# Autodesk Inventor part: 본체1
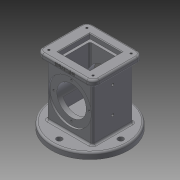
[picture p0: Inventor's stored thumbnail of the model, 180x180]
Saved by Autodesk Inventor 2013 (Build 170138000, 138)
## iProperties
Created: 2018-10
Part Number: 본체1
Material: Generic
Document SubType Name: Modeling
Designer: Administrator
Density: 1 g/cm^3
Author: Administrator
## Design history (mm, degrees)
sketch "스케치1"
  geometry: C1 r 62.5 at (0, 0); 1 further point
  constraints: 1 centre point, 1 coincident
extrude "돌출1" new body sketch "스케치1" distance "d1" = 10; taper "d2" = 0 deg
sketch "스케치2"
  geometry: C1 r 62.5 at (0, 0) reference; A1 r 50 centre (0, 0) between (0, 50) and (50, 0); 2 further points
  constraints: 4 point on circle, 1 centre point, 1 coincident
  dimensions: "d3" = 100 diameter of A1
hole "구멍1" sketch "스케치2" at (0, 50), (50, 0), (0, -50), (-50, 0) diameter "d4" = 9; stored, may be unused: countersink angle "d8" = 90 deg, drill point angle "d10" = 118 deg; dims "d5" = 6, "d6" = 4, "d7" = 2, "d9" = 8
sketch "스케치3"
  geometry: L1 (-37, 33)-(37, 33); L2 (37, 33)-(37, -33); L3 (37, -33)-(-37, -33); L4 (-37, -33)-(-37, 33); C1 r 62.5 at (0, 0) reference; 2 further points
  constraints: 8 end point, 2 midpoint, 2 parallel, 1 horizontal, 1 horizontal alignment, 1 perpendicular, 1 vertical alignment
  dimensions: "d11" = 74 distance of L1.start L1.end; "d13" = 66 distance of L1.end L2.end
extrude "돌출2" join sketch "스케치3" distance "d14" = 98; taper "d15" = 0 deg
sketch "스케치4"
  geometry: L1 (37, 33)-(-37, 33) reference; L2 (-37, 33)-(-37, -33) reference; L3 (-37, -33)-(37, -33) reference; L4 (37, -33)-(37, 33) reference; L5 (-46, 41)-(46, 41); L6 (46, 41)-(46, -41); L7 (46, -41)-(-46, -41); L8 (-46, -41)-(-46, 41); 3 further points
  constraints: 8 end point, 2 midpoint, 2 parallel, 1 horizontal, 1 horizontal alignment, 1 perpendicular, 1 vertical alignment
  dimensions: "d16" = 92 distance of L5.start L5.end; "d18" = 82 distance of L5.end L6.end
extrude "돌출3" join sketch "스케치4" distance "d19" = 10; taper "d20" = 0 deg
sketch "스케치5"
  geometry: L1 (-26, 26)-(26, 26); L2 (26, 26)-(26, -26); L3 (26, -26)-(-26, -26); L4 (-26, -26)-(-26, 26); 3 further points
  constraints: 8 end point, 2 midpoint, 2 parallel, 1 horizontal, 1 horizontal alignment, 1 perpendicular, 1 vertical alignment
  dimensions: "d21" = 52 distance of L1.start L1.end; "d23" = 52 distance of L1.end L2.end
extrude "돌출4" cut sketch "스케치5" distance "d24" = 8; taper "d25" = 0 deg
fillet "모깎기5" dims "d86" = 3
fillet "모깎기6" dims "d87" = 3
fillet "모깎기1" dims "d38" = 10
sketch "스케치8"
  geometry: L1 (-22, 22)-(22, 22); L2 (22, 22)-(22, -22); L3 (22, -22)-(-22, -22); L4 (-22, -22)-(-22, 22); 3 further points
  constraints: 8 end point, 2 midpoint, 2 parallel, 1 horizontal, 1 horizontal alignment, 1 perpendicular, 1 vertical alignment
  dimensions: "d39" = 44 distance of L1.end L2.end; "d41" = 44 distance of L1.start L1.end
extrude "돌출5" cut sketch "스케치8" distance "d42" = 74; taper "d43" = 0 deg
sketch "스케치7"
  geometry: L1 (-33, 54)-(33, 54); L2 (-62.5, 0)-(62.5, 0) reference; L3 (-33, 89)-(-30, 89); L4 (-30, 89)-(-30, 78); L5 (-30, 78)-(30, 78); L6 (30, 78)-(30, 89); L7 (30, 89)-(33, 89); L8 (33, 89)-(33, 99); L9 (-33, 99)-(-33, 89); L10 (-33, 89)-(-33, 54); L11 (33, 54)-(33, 89); 3 further points
  constraints: 20 end point, 5 parallel, 2 midpoint, 2 vertical alignment, 1 collinear, 1 horizontal, 1 perpendicular
  dimensions: "d28" = 54 distance between parallel lines of L2 L1; "d29" = 66 distance of L1.start L1.end; "d31" = 48 diameter of L5 L1; "d32" = 3 distance of L3.start L3.end; "d33" = 3 distance of L6.end L7.end; "d34" = 70 diameter of L7 L1; "d35" = 70 diameter of L3 L1; "d36" = 66 distance of L8.end L9.start
revolve "회전1" sketch "스케치7" stored, may be unused: angle "d37" = 90 deg
fillet "모깎기2" dims "d44" = 3
sketch "스케치9"
  geometry: A1 r 10 centre (-36, -31) between (-46, -31) and (-36, -41) reference; A2 r 10 centre (36, -31) between (36, -41) and (46, -31) reference; A3 r 10 centre (36, 31) between (46, 31) and (36, 41) reference; A4 r 10 centre (-36, 31) between (-36, 41) and (-46, 31) reference; 1 further point
hole "구멍2" sketch "스케치9" at (-36, -31), (36, -31), (36, 31), (-36, 31) diameter "d45" = 3.242; stored, may be unused: countersink angle "d49" = 90 deg, drill point angle "d51" = 118 deg; dims "d46" = 4, "d47" = 4, "d48" = 2, "d50" = 8
sketch "스케치10"
  geometry: C1 r 35 at (0, 0) reference; A1 r 29 centre (0, 0) between (0, 29) and (29, 0); 3 further points
  constraints: 4 point on circle, 1 centre point, 1 coincident
  dimensions: "d52" = 58 diameter of A1
hole "구멍3" sketch "스케치10" at (0, 29), (29, 0), (0, -29), (-29, 0) diameter "d53" = 3.242; stored, may be unused: countersink angle "d57" = 90 deg, drill point angle "d59" = 118 deg; dims "d54" = 4, "d55" = 4, "d56" = 2, "d58" = 6
sketch "스케치11"
  geometry: L1 (13, -32.5)-(13, 92.5) reference; L2 (-95, 61)-(-95, -1) reference; L3 (13, 30)-(-95, 30); L4 (-24, -23.063)-(-24, 92.5); L5 (-67, -26.455)-(-67, 92.5); 4 further points
  constraints: 6 end point, 4 point on line, 2 coincident, 1 midpoint, 1 parallel, 1 perpendicular
  dimensions: "d60" = 37 distance between parallel lines of L1 L4; "d61" = 43 distance between parallel lines of L4 L5
hole "구멍4" sketch "스케치11" at (-67, 30), (-24, 30) diameter "d62" = 4.134; stored, may be unused: countersink angle "d66" = 90 deg, drill point angle "d68" = 118 deg; dims "d63" = 30, "d64" = 4, "d65" = 2, "d67" = 32
sketch "스케치12"
  geometry: L1 (72, 0)-(0, 0) reference; L2 (-10, -3)-(-10, -7) reference; 4 further points
  constraints: 1 other
  dimensions: "d69" = 46 distance from line of point (36, -4) L2; "d70" = 4 distance from line of point (36, -4) L1
extrude "돌출6" join sketch "스케치12" distance "d71" = 0.5; taper "d72" = 0 deg
chamfer "모따기1" distance "d73" = 1; stored, may be unused: second distance "d74" = 2, angle "d75" = 45 deg
sketch "스케치13"
  geometry: L1 (-28, 0)-(0, 0); L2 (-24.826, 18)-(0, 18); L3 (-28, 0)-(-24.826, 18); L4 (-28, 0)-(-4.799, 0); L5 (28, 0)-(49.612, 0); L6 (28, 0)-(24.826, 18); L7 (28, 0)-(48.573, 0); L8 (0, 0)-(0, 18); 1 further point
  constraints: 16 end point, 4 horizontal, 1 coincident, 1 parallel
  dimensions: "d76" = 56 distance of L1.start L5.start; "d78" = 18 distance between parallel lines of L1 L2; "d79" = 80 deg angle of L4 L3; "d82" = 28 distance of L1.start L1.end
revolve "회전2" sketch "스케치13" stored, may be unused: angle "d83" = 90 deg
fillet "모깎기3" dims "d84" = 3
fillet "모깎기4" dims "d85" = 3
node "솔리드1"
mirror "대칭1"
